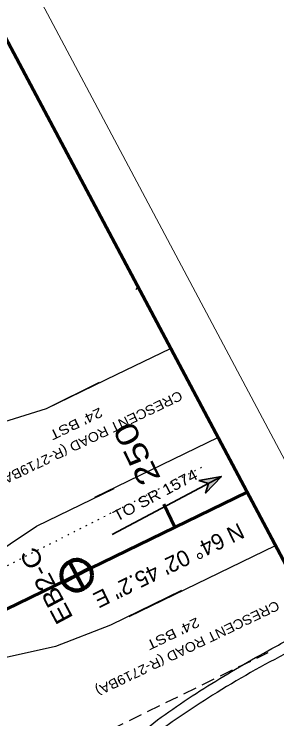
# Model space of a CAD drawing. Extents: x 2402199 to 2404507, y 568050 to 571478.
# Drawn here: x 2402576.7 to 2402658.4, y 570995.3 to 571214.3 of the extents above; entities that cross this region are included whole.
import ezdxf
from ezdxf.enums import TextEntityAlignment as Align

# ---------------------------------------------------------------- set-up
doc = ezdxf.new("R2010")
doc.units = 0
doc.header["$LTSCALE"] = 1.4
doc.linetypes.add('DOTTED', pattern=[1.5, 0.3, -1.2])
doc.linetypes.add('MEDIUM_DASHED', pattern=[4.5, 3, -1.5])
for name, color, linetype, lineweight in [('1', 7, 'Continuous', 35), ('10', 7, 'Continuous', 25), ('11', 7, 'Continuous', 25), ('17', 7, 'MEDIUM_DASHED', 35), ('27', 7, 'Continuous', 80), ('28', 7, 'Continuous', 25), ('3', 7, 'Continuous', 25), ('42', 7, 'Continuous', 25), ('6', 7, 'Continuous', 35), ('62', 7, 'Continuous', 60), ('63', 7, 'Continuous', 35)]:
    doc.layers.add(name, color=color, linetype=linetype, lineweight=lineweight)
doc.layers.add('23', color=7, linetype='Continuous')

msp = doc.modelspace()

# ---------------------------------------------------------------- hatches: boundary and pattern name
at = {"layer": '10'}
msp.add_hatch(color=256, dxfattribs=at).paths.add_polyline_path([(2402634.146, 571069.401), (2402641.163, 571070.583), (2402636.259, 571065.427), (2402637.189, 571068.47)])

# ---------------------------------------------------------------- linework, layer by layer
at = {"layer": '1', "lineweight": 25}
msp.add_line((2402614.654, 571128.713), (2402615.155, 571129.657), dxfattribs=at)
at = {"layer": '10', "lineweight": 35}
msp.add_lwpolyline([(2402634.146, 571069.401), (2402641.163, 571070.583), (2402636.259, 571065.427), (2402637.189, 571068.47)], close=True, dxfattribs=at)
at = {"layer": '11', "linetype": 'DOTTED'}
msp.add_line((2402548.422, 571029.708), (2402635.481, 571073.714), dxfattribs=at)
at = {"layer": '17', "lineweight": 25}
msp.add_line((2402550.332, 570964.289), (2402655.74, 571015.937), dxfattribs=at)
msp.add_arc((2399953.615, 569708.021), 2887.133, 22.84472, 31.18511, dxfattribs=at)
at = {"layer": '27', "lineweight": 35}
msp.add_line((2402641.163, 571070.583), (2402607.25, 571052.551), dxfattribs=at)
at = {"layer": '27'}
for p, q in [((2402593.948, 571044.12), (2402598.402, 571035.744)), ((2402600.363, 571042.158), (2402591.987, 571037.706)), ((2402591.962, 571037.753), (2402591.987, 571037.706))]:
    msp.add_line(p, q, dxfattribs=at)
for points in [[(2402600.363, 571042.158), (2402596.175, 571039.932), (2402593.948, 571044.12), (2402593.902, 571044.095)], [(2402591.987, 571037.706), (2402596.175, 571039.932), (2402598.402, 571035.744)]]:
    msp.add_lwpolyline(points, dxfattribs=at)
msp.add_circle((2402596.174, 571039.932), 4.743, dxfattribs=at)
for start, end in [(28, 118.64427), (207.35574, 298)]:
    msp.add_arc((2402596.174, 571039.932), 4.743, start, end, dxfattribs=at)
at = {"layer": '28'}
for p, q in [((2402608.59, 571102.32), (2402625.388, 571110.412)), ((2402640.129, 571082.687), (2402601.73, 571064.065)), ((2402612.508, 571027.095), (2402657.957, 571049.158))]:
    msp.add_line(p, q, dxfattribs=at)
for points in [[(2402608.658, 571102.353), (2402586.696, 571091.641), (2402563.737, 571084.481), (2402534.511, 571079.781), (2402500.05, 571089.933), (2402459.199, 571135.878), (2402421.36, 571200.686), (2402420.824, 571201.541)], [(2402567.227, 571044.225), (2402583.703, 571055.147), (2402607.861, 571066.866)], [(2402628.741, 571035.161), (2402606.667, 571024.367), (2402589.598, 571017.725), (2402549.917, 571008.987), (2402537.926, 571009.435), (2402536.327, 571012.897), (2402546.371, 571025.723), (2402567.227, 571044.225)]]:
    msp.add_lwpolyline(points, dxfattribs=at)
msp.add_spline([(2402672.797, 571021.249), (2402662.311, 571016.13), (2402638.421, 571002.609), (2402618.59, 570989.004), (2402606.097, 570978.965)], degree=3, dxfattribs=at)
at = {"layer": '3'}
for points in [[(2402603.164, 571099.846), (2402586.696, 571091.641), (2402563.737, 571084.481), (2402534.511, 571079.781), (2402500.05, 571089.933), (2402459.199, 571135.878), (2402421.36, 571200.686), (2402420.824, 571201.541)], [(2402567.227, 571044.225), (2402583.703, 571055.147), (2402607.861, 571066.866)], [(2402628.741, 571035.161), (2402606.667, 571024.367), (2402589.598, 571017.725), (2402549.917, 571008.987), (2402537.926, 571009.435), (2402536.327, 571012.897), (2402546.371, 571025.723), (2402567.227, 571044.225)]]:
    msp.add_lwpolyline(points, dxfattribs=at)
at = {"layer": '42'}
msp.add_spline([(2402604.139, 570980.327), (2402619.016, 570993.164), (2402638.22, 571006.292), (2402658.089, 571017.786), (2402671.023, 571024.586)], degree=3, dxfattribs=at)
at = {"layer": '6', "lineweight": 60}
msp.add_line((2402626.727, 571054.85), (2402623.226, 571062.044), dxfattribs=at)
at = {"layer": '62'}
msp.add_line((2402379.217, 570934.377), (2402649.132, 571065.756), dxfattribs=at)
msp.add_arc((2399929.798, 569697.989), 2887.133, 22.84477, 31.13893, dxfattribs=at)
at = {"layer": '63', "lineweight": 13}
msp.add_line((2402778.178, 570855.005), (2402538.748, 571305.309), dxfattribs=at)
at = {"layer": '63', "lineweight": 60}
msp.add_line((2402531.138, 571287.671), (2402757.403, 570862.128), dxfattribs=at)
at = {"layer": '63', "lineweight": 25}
msp.add_line((2402581.4, 571193.14), (2402581.356, 571193.117), dxfattribs=at)

# ---------------------------------------------------------------- texts
at = {"layer": '23'}
for s, height, rotation, width, p in [('CRESCENT ROAD (R-2719BA)', 3, 205.547, 1.1, (2402599.838, 571083.818)), ("   24' BST", 3, 205.547, 1.25, (2402597.25, 571089.231)), ('TO SR 1574', 3.375, 28, 1.15, (2402621.409, 571063.27)), ('CRESCENT ROAD (R-2719BA)', 3, 205.547, 1.1, (2402629.978, 571018.573)), ("   24' BST", 3, 205.547, 1.25, (2402627.391, 571023.986))]:
    msp.add_text(s, height=height, rotation=rotation, dxfattribs=dict(at, width=width)).set_placement(p, align=Align.CENTER)
at = {"layer": '27', "width": 1.15}
msp.add_text('EB2-C', height=5.625, rotation=118, dxfattribs=at).set_placement((2402589.253, 571037.962), align=Align.CENTER)
at = {"layer": '63', "width": 1.3}
msp.add_text('250', height=7, rotation=115.954, dxfattribs=at).set_placement((2402617.988, 571079.141), align=Align.CENTER)
at = {"layer": '63'}
msp.add_text('N 64° 02\' 45.2" E', height=5, rotation=205.954, dxfattribs=at).set_placement((2402623.725, 571045.197), align=Align.CENTER)

doc.saveas('drawing.dxf')
